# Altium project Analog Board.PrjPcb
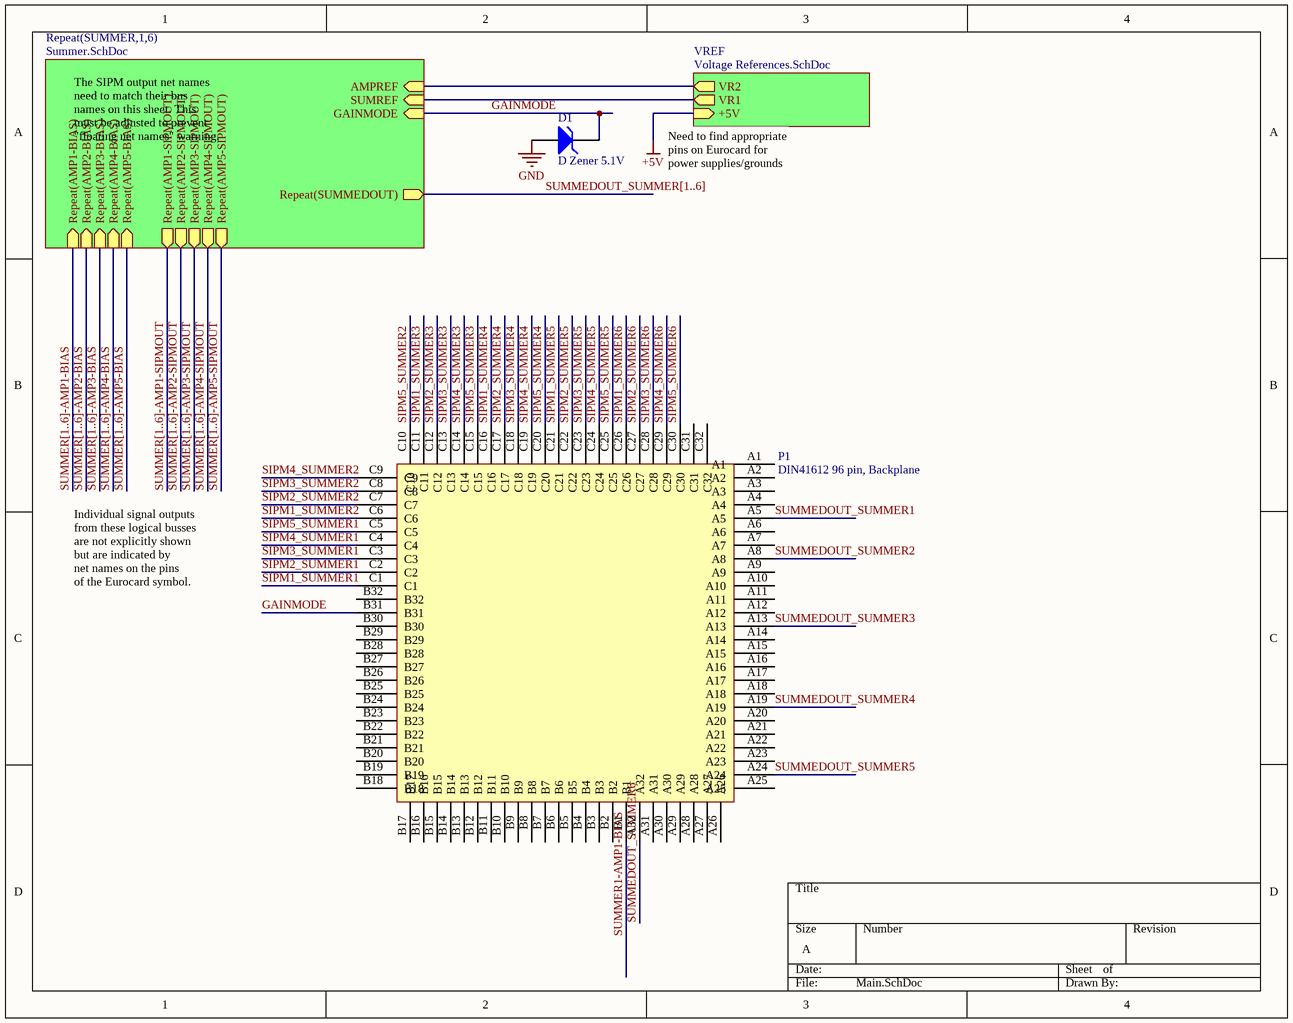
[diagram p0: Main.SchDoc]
4 sheets, 880 parts. Net scope: hierarchical (ports join the sheet entries above them; power ports are global).
Board files: Test PCB.PcbDoc, Amplifier Board.PcbDoc
Sheets:
  Main.SchDoc
    SUMMER1 = Summer.SchDoc
      AMP1 = Amplifier.SchDoc
      AMP2 = Amplifier.SchDoc
      AMP3 = Amplifier.SchDoc
      AMP4 = Amplifier.SchDoc
      AMP5 = Amplifier.SchDoc
    SUMMER2 = Summer.SchDoc
      AMP1 = Amplifier.SchDoc
      AMP2 = Amplifier.SchDoc
      AMP3 = Amplifier.SchDoc
      AMP4 = Amplifier.SchDoc
      AMP5 = Amplifier.SchDoc
    SUMMER3 = Summer.SchDoc
      AMP1 = Amplifier.SchDoc
      AMP2 = Amplifier.SchDoc
      AMP3 = Amplifier.SchDoc
      AMP4 = Amplifier.SchDoc
      AMP5 = Amplifier.SchDoc
    SUMMER4 = Summer.SchDoc
      AMP1 = Amplifier.SchDoc
      AMP2 = Amplifier.SchDoc
      AMP3 = Amplifier.SchDoc
      AMP4 = Amplifier.SchDoc
      AMP5 = Amplifier.SchDoc
    SUMMER5 = Summer.SchDoc
      AMP1 = Amplifier.SchDoc
      AMP2 = Amplifier.SchDoc
      AMP3 = Amplifier.SchDoc
      AMP4 = Amplifier.SchDoc
      AMP5 = Amplifier.SchDoc
    SUMMER6 = Summer.SchDoc
      AMP1 = Amplifier.SchDoc
      AMP2 = Amplifier.SchDoc
      AMP3 = Amplifier.SchDoc
      AMP4 = Amplifier.SchDoc
      AMP5 = Amplifier.SchDoc
    VREF = Voltage References.SchDoc

## Sheet Main.SchDoc
size A

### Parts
D1  D Zener 5.1V  [DIODE-0.7]
P1  DIN41612 96 pin, Backplane  [EURO2.54-2V96]

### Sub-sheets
Repeat(SUMMER,1,6) = Summer.SchDoc: Repeat(AMP1-BIAS) (in), Repeat(SUMMEDOUT) (out), Repeat(AMP2-SIPMOUT) (out), Repeat(AMP5-SIPMOUT) (out), Repeat(AMP1-SIPMOUT) (out), Repeat(AMP3-SIPMOUT) (out), Repeat(AMP4-SIPMOUT) (out), Repeat(AMP2-BIAS) (in), Repeat(AMP3-BIAS) (in), Repeat(AMP4-BIAS) (in), Repeat(AMP5-BIAS) (in), AMPREF (in), SUMREF (in), GAINMODE (in)
VREF = Voltage References.SchDoc: VR2 (out), VR1 (out), +5V (in)

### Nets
GND: D1.1(A)
GAINMODE: D1.2(K) P1.B31 ; sheet Repeat(SUMMER,1,6)/GAINMODE
SIPM1_SUMMER1: P1.C1
SIPM1_SUMMER2: P1.C6
SIPM1_SUMMER3: P1.C11
SIPM1_SUMMER4: P1.C16
SIPM1_SUMMER5: P1.C21
SIPM1_SUMMER6: P1.C26
SIPM2_SUMMER1: P1.C2
SIPM2_SUMMER2: P1.C7
SIPM2_SUMMER3: P1.C12
SIPM2_SUMMER4: P1.C17
SIPM2_SUMMER5: P1.C22
SIPM2_SUMMER6: P1.C27
SIPM3_SUMMER1: P1.C3
SIPM3_SUMMER2: P1.C8
SIPM3_SUMMER3: P1.C13
SIPM3_SUMMER4: P1.C18
SIPM3_SUMMER5: P1.C23
SIPM3_SUMMER6: P1.C28
SIPM4_SUMMER1: P1.C4
SIPM4_SUMMER2: P1.C9
SIPM4_SUMMER3: P1.C14
SIPM4_SUMMER4: P1.C19
SIPM4_SUMMER5: P1.C24
SIPM4_SUMMER6: P1.C29
SIPM5_SUMMER1: P1.C5
SIPM5_SUMMER2: P1.C10
SIPM5_SUMMER3: P1.C15
SIPM5_SUMMER4: P1.C20
SIPM5_SUMMER5: P1.C25
SIPM5_SUMMER6: P1.C30
SUMMEDOUT_SUMMER1: P1.A5
SUMMEDOUT_SUMMER2: P1.A8
SUMMEDOUT_SUMMER3: P1.A13
SUMMEDOUT_SUMMER4: P1.A19
SUMMEDOUT_SUMMER5: P1.A24
SUMMEDOUT_SUMMER6: P1.A32
SUMMER1-AMP1-BIAS: P1.B1
NetR25_2: sheet Repeat(SUMMER,1,6)/SUMREF, sheet VREF/VR1
NetR26_2: sheet Repeat(SUMMER,1,6)/AMPREF, sheet VREF/VR2

Not connected (* = marked no-connect by the designer): P1 A1 A2 A3 A4 A6 A7 A9 A10 A11 A12 A14 A15 A16 A17 A18 A20 A21 A22 A23 A25 A26 A27 A28 A29 A30 A31 B2 B3 B4 B5 B6 B7 B8 B9 B10 B11 B12 B13 B14 B15 B16 B17 B18 B19 B20 B21 B22 B23 B24 B25 B26 B27 B28 B29 B30 B32 C31 C32

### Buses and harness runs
bus SUMMEDOUT_SUMMER[1..6]
bus SUMMER[1..6]-AMP1-BIAS
bus SUMMER[1..6]-AMP1-SIPMOUT
bus SUMMER[1..6]-AMP2-BIAS
bus SUMMER[1..6]-AMP2-SIPMOUT
bus SUMMER[1..6]-AMP3-BIAS
bus SUMMER[1..6]-AMP3-SIPMOUT
bus SUMMER[1..6]-AMP4-BIAS
bus SUMMER[1..6]-AMP4-SIPMOUT
bus SUMMER[1..6]-AMP5-BIAS
bus SUMMER[1..6]-AMP5-SIPMOUT

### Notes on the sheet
- The SIPM output net names need to match their bus names on this sheet. This must be adjusted to prevent "floating net names" warning.
- Need to find appropriate pins on Eurocard for power supplies/grounds
- Individual signal outputs
  from these logical busses
  are not explicitly shown
  but are indicated by
  net names on the pins
  of the Eurocard symbol.

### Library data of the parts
D1 = D Zener: Zener Diode

## Sheet Summer.SchDoc
size A
Used 6 times, as channels SUMMER1, SUMMER2, SUMMER3, SUMMER4, SUMMER5, SUMMER6. Parts and nets are listed once, with the designators drawn on the sheet.
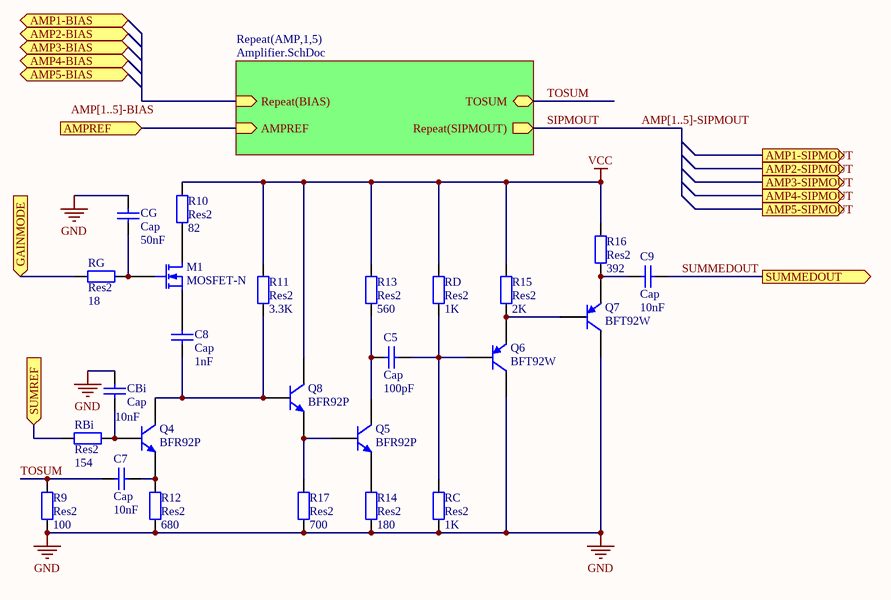
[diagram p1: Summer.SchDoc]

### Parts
C5  Cap  value 100pF  [RESC0603L]
C7  Cap  value 10nF  [RESC0603L]
C8  Cap  value 1nF  [RESC0603L]
C9  Cap  value 10nF  [RESC0603L]
CBi  Cap  value 10nF  [RESC0603L]
CG  Cap  value 50nF  [RESC0603L]
M1  MOSFET-N  [SOT-143]
Q4  BFR92P  [SOT23_N]
Q5  BFR92P  [SOT23_N]
Q6  BFT92W  [SOT323_L]
Q7  BFT92W  [SOT323_L]
Q8  BFR92P  [SOT23_N]
R9  Res2  value 100  [RESC0603L]
R10  Res2  value 82  [RESC0603L]
R11  Res2  value 3.3K  [RESC0603L]
R12  Res2  value 680  [RESC0603L]
R13  Res2  value 560  [RESC0603L]
R14  Res2  value 180  [RESC0603L]
R15  Res2  value 2K  [RESC0603L]
R16  Res2  value 392  [RESC0603L]
R17  Res2  value 700  [RESC0603L]
RBi  Res2  value 154  [RESC0603L]
RC  Res2  value 1K  [RESC0603L]
RD  Res2  value 1K  [RESC0603L]
RG  Res2  value 18  [RESC0603L]

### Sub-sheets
Repeat(AMP,1,5) = Amplifier.SchDoc: Repeat(BIAS) (in), TOSUM (bidir), Repeat(SIPMOUT) (out), AMPREF (in)

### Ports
AMP1-BIAS (in), AMP1-SIPMOUT (out), AMP2-BIAS (in), AMP2-SIPMOUT (out), AMP3-BIAS (in), AMP3-SIPMOUT (out), AMP4-BIAS (in), AMP4-SIPMOUT (out), AMP5-BIAS (in), AMP5-SIPMOUT (out), AMPREF (in), GAINMODE (in), SUMMEDOUT (out), SUMREF (in)

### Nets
GND: CBi.2 CG.2 Q6.3(C) Q7.3(C) R9.1 R12.1 R14.1 R17.1 RC.1
VCC: Q8.3(C) R10.2 R11.2 R13.2 R15.2 R16.2 RD.2
AMPREF: port AMPREF, sheet Repeat(AMP,1,5)/AMPREF
GAINMODE: RG.2 ; port GAINMODE
SUMMEDOUT: C9.2 ; port SUMMEDOUT
SUMREF: RBi.1 ; port SUMREF
TOSUM: C7.1 R9.2 ; sheet Repeat(AMP,1,5)/TOSUM
NetC5_1: C5.1 Q5.3(C) R13.1
NetC5_2: C5.2 Q6.1(B) RC.2 RD.1
NetC7_2: C7.2 Q4.2(E) R12.2
NetC8_1: C8.1 Q4.3(C) Q8.1(B) R11.1
NetC8_2: C8.2 M1.3(S)
NetC9_1: C9.1 Q7.2(E) R16.1
NetCBi_1: CBi.1 Q4.1(B) RBi.2
NetCG_1: CG.1 M1.1(G) RG.1
NetM1_4: M1.4(D) R10.1
NetQ5_1: Q5.1(B) Q8.2(E) R17.2
NetQ5_2: Q5.2(E) R14.2
NetQ6_2: Q6.2(E) Q7.1(B) R15.1

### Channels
SUMMER1: designators end in _SUMMER1; ports AMP1-BIAS=open AMP1-SIPMOUT=open AMP2-BIAS=open AMP2-SIPMOUT=open AMP3-BIAS=open AMP3-SIPMOUT=open AMP4-BIAS=open AMP4-SIPMOUT=open AMP5-BIAS=open AMP5-SIPMOUT=open AMPREF=NetR26_2 GAINMODE=GAINMODE SUMMEDOUT=SUMMEDOUT_SUMMER1 SUMREF=NetR25_2
SUMMER2: designators end in _SUMMER2; ports AMP1-BIAS=open AMP1-SIPMOUT=open AMP2-BIAS=open AMP2-SIPMOUT=open AMP3-BIAS=open AMP3-SIPMOUT=open AMP4-BIAS=open AMP4-SIPMOUT=open AMP5-BIAS=open AMP5-SIPMOUT=open AMPREF=NetR26_2 GAINMODE=GAINMODE SUMMEDOUT=SUMMEDOUT_SUMMER2 SUMREF=NetR25_2
SUMMER3: designators end in _SUMMER3; ports AMP1-BIAS=open AMP1-SIPMOUT=open AMP2-BIAS=open AMP2-SIPMOUT=open AMP3-BIAS=open AMP3-SIPMOUT=open AMP4-BIAS=open AMP4-SIPMOUT=open AMP5-BIAS=open AMP5-SIPMOUT=open AMPREF=NetR26_2 GAINMODE=GAINMODE SUMMEDOUT=SUMMEDOUT_SUMMER3 SUMREF=NetR25_2
SUMMER4: designators end in _SUMMER4; ports AMP1-BIAS=open AMP1-SIPMOUT=open AMP2-BIAS=open AMP2-SIPMOUT=open AMP3-BIAS=open AMP3-SIPMOUT=open AMP4-BIAS=open AMP4-SIPMOUT=open AMP5-BIAS=open AMP5-SIPMOUT=open AMPREF=NetR26_2 GAINMODE=GAINMODE SUMMEDOUT=SUMMEDOUT_SUMMER4 SUMREF=NetR25_2
SUMMER5: designators end in _SUMMER5; ports AMP1-BIAS=open AMP1-SIPMOUT=open AMP2-BIAS=open AMP2-SIPMOUT=open AMP3-BIAS=open AMP3-SIPMOUT=open AMP4-BIAS=open AMP4-SIPMOUT=open AMP5-BIAS=open AMP5-SIPMOUT=open AMPREF=NetR26_2 GAINMODE=GAINMODE SUMMEDOUT=SUMMEDOUT_SUMMER5 SUMREF=NetR25_2
SUMMER6: designators end in _SUMMER6; ports AMP1-BIAS=open AMP1-SIPMOUT=open AMP2-BIAS=open AMP2-SIPMOUT=open AMP3-BIAS=open AMP3-SIPMOUT=open AMP4-BIAS=open AMP4-SIPMOUT=open AMP5-BIAS=open AMP5-SIPMOUT=open AMPREF=NetR26_2 GAINMODE=GAINMODE SUMMEDOUT=SUMMEDOUT_SUMMER6 SUMREF=NetR25_2

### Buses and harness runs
bus AMP[1..5]-BIAS
bus AMP[1..5]-SIPMOUT

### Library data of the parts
C5 C7-C9 CBi CG = Cap: Capacitor
M1 = MOSFET-N: N-Channel MOSFET; PackageDocument: 1995/1996
Q4 Q5 Q8 = BFR92A: NPN 5 GHz Wideband Transistor
Q6 Q7 = BFT92W: PNP 4 GHz Wideband Transistor
R9-R17 RBi RC RD RG = Res2: Resistor

## Sheet Amplifier.SchDoc
size A
Used 30 times, as channels SUMMER1/AMP1, SUMMER1/AMP2, SUMMER1/AMP3, SUMMER1/AMP4, SUMMER1/AMP5, SUMMER2/AMP1, SUMMER2/AMP2, SUMMER2/AMP3, SUMMER2/AMP4, SUMMER2/AMP5, SUMMER3/AMP1, SUMMER3/AMP2, SUMMER3/AMP3, SUMMER3/AMP4, SUMMER3/AMP5, SUMMER4/AMP1, SUMMER4/AMP2, SUMMER4/AMP3, SUMMER4/AMP4, SUMMER4/AMP5, SUMMER5/AMP1, SUMMER5/AMP2, SUMMER5/AMP3, SUMMER5/AMP4, SUMMER5/AMP5, SUMMER6/AMP1, SUMMER6/AMP2, SUMMER6/AMP3, SUMMER6/AMP4, SUMMER6/AMP5. Parts and nets are listed once, with the designators drawn on the sheet.
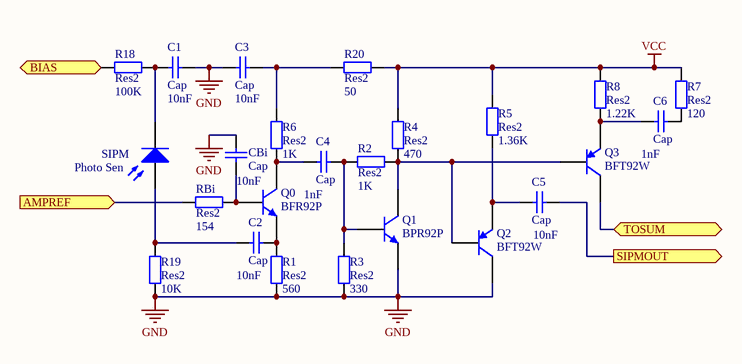
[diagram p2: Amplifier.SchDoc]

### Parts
C1  Cap  value 10nF  [RESC0603L]
C2  Cap  value 10nF  [RESC0603L]
C3  Cap  value 10nF  [RESC0603L]
C4  Cap  value 1nF  [RESC0603L]
C5  Cap  value 10nF  [RESC0603L]
C6  Cap  value 1nF  [RESC0603L]
CBi  Cap  value 10nF  [RESC0603L]
Q0  BFR92P  [SOT23_N]
Q1  BPR92P  [SOT23_N]
Q2  BFT92W  [SOT323_L]
Q3  BFT92W  [SOT323_L]
R1  Res2  value 560  [RESC0603L]
R2  Res2  value 1K  [RESC0603L]
R3  Res2  value 330  [RESC0603L]
R4  Res2  value 470  [RESC0603L]
R5  Res2  value 1.36K  [RESC0603L]
R6  Res2  value 1K  [RESC0603L]
R7  Res2  value 120  [RESC0603L]
R8  Res2  value 1.22K  [RESC0603L]
R18  Res2  value 100K  [RESC0603L]
R19  Res2  value 10K  [RESC0603L]
R20  Res2  value 50  [RESC0603L]
RBi  Res2  value 154  [RESC0603L]
SIPM  Photo Sen  [Photonique SiPM]

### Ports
AMPREF (in), BIAS (in), SIPMOUT (out), TOSUM (bidir)

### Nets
GND: C1.2 C3.1 CBi.2 Q1.2(E) Q2.3(C) R1.1 R3.1 R19.1
VCC: R4.2 R5.2 R7.2 R8.2 R20.2
AMPREF: RBi.1 ; port AMPREF
BIAS: R18.1 ; port BIAS
SIPMOUT: C5.2 ; port SIPMOUT
TOSUM: Q3.3(C) ; port TOSUM
NetC1_1: C1.1 R18.2 SIPM.2(K)
NetC2_1: C2.1 R19.2 SIPM.1(A)
NetC2_2: C2.2 Q0.2(E) R1.2
NetC3_2: C3.2 R6.2 R20.1
NetC4_1: C4.1 Q0.3(C) R6.1
NetC4_2: C4.2 Q1.1(B) R2.1 R3.2
NetC5_1: C5.1 Q2.2(E) R5.1
NetC6_1: C6.1 Q3.2(E) R8.1
NetC6_2: C6.2 R7.1
NetCBi_1: CBi.1 Q0.1(B) RBi.2
NetQ1_3: Q1.3(C) Q2.1(B) Q3.1(B) R2.2 R4.1

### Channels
SUMMER1/AMP1: designators end in _AMP1; ports AMPREF=NetR26_2 BIAS=NetR18_AMP1_1 SIPMOUT=SIPMOUT1_SUMMER1 TOSUM=TOSUM_SUMMER1
SUMMER1/AMP2: designators end in _AMP2; ports AMPREF=NetR26_2 BIAS=NetR18_AMP2_1 SIPMOUT=SIPMOUT2_SUMMER1 TOSUM=TOSUM_SUMMER1
SUMMER1/AMP3: designators end in _AMP3; ports AMPREF=NetR26_2 BIAS=NetR18_AMP3_1 SIPMOUT=SIPMOUT3_SUMMER1 TOSUM=TOSUM_SUMMER1
SUMMER1/AMP4: designators end in _AMP4; ports AMPREF=NetR26_2 BIAS=NetR18_AMP4_1 SIPMOUT=SIPMOUT4_SUMMER1 TOSUM=TOSUM_SUMMER1
SUMMER1/AMP5: designators end in _AMP5; ports AMPREF=NetR26_2 BIAS=NetR18_AMP5_1 SIPMOUT=SIPMOUT5_SUMMER1 TOSUM=TOSUM_SUMMER1
SUMMER2/AMP1: designators end in _AMP6; ports AMPREF=NetR26_2 BIAS=NetR18_AMP6_1 SIPMOUT=SIPMOUT1_SUMMER2 TOSUM=TOSUM_SUMMER2
SUMMER2/AMP2: designators end in _AMP7; ports AMPREF=NetR26_2 BIAS=NetR18_AMP7_1 SIPMOUT=SIPMOUT2_SUMMER2 TOSUM=TOSUM_SUMMER2
SUMMER2/AMP3: designators end in _AMP8; ports AMPREF=NetR26_2 BIAS=NetR18_AMP8_1 SIPMOUT=SIPMOUT3_SUMMER2 TOSUM=TOSUM_SUMMER2
SUMMER2/AMP4: designators end in _AMP9; ports AMPREF=NetR26_2 BIAS=NetR18_AMP9_1 SIPMOUT=SIPMOUT4_SUMMER2 TOSUM=TOSUM_SUMMER2
SUMMER2/AMP5: designators end in _AMP10; ports AMPREF=NetR26_2 BIAS=NetR18_AMP10_1 SIPMOUT=SIPMOUT5_SUMMER2 TOSUM=TOSUM_SUMMER2
SUMMER3/AMP1: designators end in _AMP11; ports AMPREF=NetR26_2 BIAS=NetR18_AMP11_1 SIPMOUT=SIPMOUT1_SUMMER3 TOSUM=TOSUM_SUMMER3
SUMMER3/AMP2: designators end in _AMP12; ports AMPREF=NetR26_2 BIAS=NetR18_AMP12_1 SIPMOUT=SIPMOUT2_SUMMER3 TOSUM=TOSUM_SUMMER3
SUMMER3/AMP3: designators end in _AMP13; ports AMPREF=NetR26_2 BIAS=NetR18_AMP13_1 SIPMOUT=SIPMOUT3_SUMMER3 TOSUM=TOSUM_SUMMER3
SUMMER3/AMP4: designators end in _AMP14; ports AMPREF=NetR26_2 BIAS=NetR18_AMP14_1 SIPMOUT=SIPMOUT4_SUMMER3 TOSUM=TOSUM_SUMMER3
SUMMER3/AMP5: designators end in _AMP15; ports AMPREF=NetR26_2 BIAS=NetR18_AMP15_1 SIPMOUT=SIPMOUT5_SUMMER3 TOSUM=TOSUM_SUMMER3
SUMMER4/AMP1: designators end in _AMP16; ports AMPREF=NetR26_2 BIAS=NetR18_AMP16_1 SIPMOUT=SIPMOUT1_SUMMER4 TOSUM=TOSUM_SUMMER4
SUMMER4/AMP2: designators end in _AMP17; ports AMPREF=NetR26_2 BIAS=NetR18_AMP17_1 SIPMOUT=SIPMOUT2_SUMMER4 TOSUM=TOSUM_SUMMER4
SUMMER4/AMP3: designators end in _AMP18; ports AMPREF=NetR26_2 BIAS=NetR18_AMP18_1 SIPMOUT=SIPMOUT3_SUMMER4 TOSUM=TOSUM_SUMMER4
SUMMER4/AMP4: designators end in _AMP19; ports AMPREF=NetR26_2 BIAS=NetR18_AMP19_1 SIPMOUT=SIPMOUT4_SUMMER4 TOSUM=TOSUM_SUMMER4
SUMMER4/AMP5: designators end in _AMP20; ports AMPREF=NetR26_2 BIAS=NetR18_AMP20_1 SIPMOUT=SIPMOUT5_SUMMER4 TOSUM=TOSUM_SUMMER4
SUMMER5/AMP1: designators end in _AMP21; ports AMPREF=NetR26_2 BIAS=NetR18_AMP21_1 SIPMOUT=SIPMOUT1_SUMMER5 TOSUM=TOSUM_SUMMER5
SUMMER5/AMP2: designators end in _AMP22; ports AMPREF=NetR26_2 BIAS=NetR18_AMP22_1 SIPMOUT=SIPMOUT2_SUMMER5 TOSUM=TOSUM_SUMMER5
SUMMER5/AMP3: designators end in _AMP23; ports AMPREF=NetR26_2 BIAS=NetR18_AMP23_1 SIPMOUT=SIPMOUT3_SUMMER5 TOSUM=TOSUM_SUMMER5
SUMMER5/AMP4: designators end in _AMP24; ports AMPREF=NetR26_2 BIAS=NetR18_AMP24_1 SIPMOUT=SIPMOUT4_SUMMER5 TOSUM=TOSUM_SUMMER5
SUMMER5/AMP5: designators end in _AMP25; ports AMPREF=NetR26_2 BIAS=NetR18_AMP25_1 SIPMOUT=SIPMOUT5_SUMMER5 TOSUM=TOSUM_SUMMER5
SUMMER6/AMP1: designators end in _AMP26; ports AMPREF=NetR26_2 BIAS=NetR18_AMP26_1 SIPMOUT=SIPMOUT1_SUMMER6 TOSUM=TOSUM_SUMMER6
SUMMER6/AMP2: designators end in _AMP27; ports AMPREF=NetR26_2 BIAS=NetR18_AMP27_1 SIPMOUT=SIPMOUT2_SUMMER6 TOSUM=TOSUM_SUMMER6
SUMMER6/AMP3: designators end in _AMP28; ports AMPREF=NetR26_2 BIAS=NetR18_AMP28_1 SIPMOUT=SIPMOUT3_SUMMER6 TOSUM=TOSUM_SUMMER6
SUMMER6/AMP4: designators end in _AMP29; ports AMPREF=NetR26_2 BIAS=NetR18_AMP29_1 SIPMOUT=SIPMOUT4_SUMMER6 TOSUM=TOSUM_SUMMER6
SUMMER6/AMP5: designators end in _AMP30; ports AMPREF=NetR26_2 BIAS=NetR18_AMP30_1 SIPMOUT=SIPMOUT5_SUMMER6 TOSUM=TOSUM_SUMMER6

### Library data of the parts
C1-C6 CBi = Cap: Capacitor
Q0 Q1 = BFR92A: NPN 5 GHz Wideband Transistor
Q2 Q3 = BFT92W: PNP 4 GHz Wideband Transistor
R1-R8 R18-R20 RBi = Res2: Resistor
SIPM = Photo Sen: Photosensitive Diode

## Sheet Voltage References.SchDoc
size A
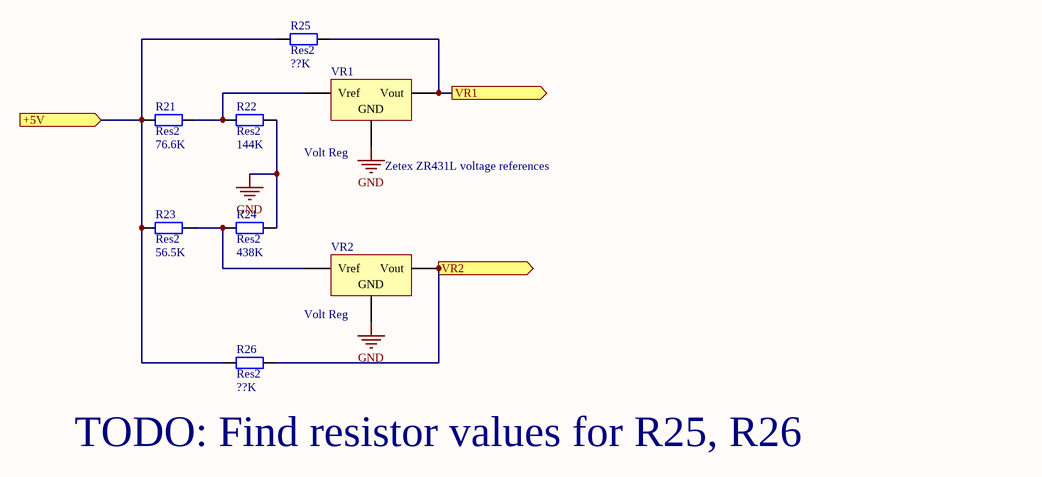
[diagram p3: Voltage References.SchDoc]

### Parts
R21  Res2  value 76.6K  [RESC0603L]
R22  Res2  value 144K  [RESC0603L]
R23  Res2  value 56.5K  [RESC3216L]
R24  Res2  value 438K  [RESC0603L]
R25  Res2  value ??K  [RESC0603L]
R26  Res2  value ??K  [RESC0603L]
VR1  Volt Reg  [SOT23_L]
VR2  Volt Reg  [SOT23_L]

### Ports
+5V (in), VR1 (out), VR2 (out)

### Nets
+5V: R21.1 R23.1 R25.1 R26.1 ; port +5V
GND: R22.2 R24.2 VR1.2(GND) VR2.2(GND)
NetR21_2: R21.2 R22.1 VR1.1(Vref)
NetR23_2: R23.2 R24.1 VR2.1(Vref)
NetR25_2: R25.2 VR1.3(Vout) ; port VR1
NetR26_2: R26.2 VR2.3(Vout) ; port VR2

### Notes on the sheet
- (near VR1) Zetex ZR431L voltage references
- (near R26) TODO: Find resistor values for R25, R26

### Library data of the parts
R21-R26 = Res2: Resistor
VR1 VR2 = Volt Reg: Voltage Regulator

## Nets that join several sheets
GND: Main (D1.1), SUMMER1 (9 pins), SUMMER1/AMP1 (8 pins), SUMMER1/AMP2 (8 pins), SUMMER1/AMP3 (8 pins), SUMMER1/AMP4 (8 pins), SUMMER1/AMP5 (8 pins), SUMMER2 (9 pins), SUMMER2/AMP1 (8 pins), SUMMER2/AMP2 (8 pins), SUMMER2/AMP3 (8 pins), SUMMER2/AMP4 (8 pins), SUMMER2/AMP5 (8 pins), SUMMER3 (9 pins), SUMMER3/AMP1 (8 pins), SUMMER3/AMP2 (8 pins), SUMMER3/AMP3 (8 pins), SUMMER3/AMP4 (8 pins), SUMMER3/AMP5 (8 pins), SUMMER4 (9 pins), SUMMER4/AMP1 (8 pins), SUMMER4/AMP2 (8 pins), SUMMER4/AMP3 (8 pins), SUMMER4/AMP4 (8 pins), SUMMER4/AMP5 (8 pins), SUMMER5 (9 pins), SUMMER5/AMP1 (8 pins), SUMMER5/AMP2 (8 pins), SUMMER5/AMP3 (8 pins), SUMMER5/AMP4 (8 pins), SUMMER5/AMP5 (8 pins), SUMMER6 (9 pins), SUMMER6/AMP1 (8 pins), SUMMER6/AMP2 (8 pins), SUMMER6/AMP3 (8 pins), SUMMER6/AMP4 (8 pins), SUMMER6/AMP5 (8 pins), Voltage References (R22.2 R24.2 VR1.2 VR2.2)
VCC: SUMMER1 (7 pins), SUMMER1/AMP1 (5 pins), SUMMER1/AMP2 (5 pins), SUMMER1/AMP3 (5 pins), SUMMER1/AMP4 (5 pins), SUMMER1/AMP5 (5 pins), SUMMER2 (7 pins), SUMMER2/AMP1 (5 pins), SUMMER2/AMP2 (5 pins), SUMMER2/AMP3 (5 pins), SUMMER2/AMP4 (5 pins), SUMMER2/AMP5 (5 pins), SUMMER3 (7 pins), SUMMER3/AMP1 (5 pins), SUMMER3/AMP2 (5 pins), SUMMER3/AMP3 (5 pins), SUMMER3/AMP4 (5 pins), SUMMER3/AMP5 (5 pins), SUMMER4 (7 pins), SUMMER4/AMP1 (5 pins), SUMMER4/AMP2 (5 pins), SUMMER4/AMP3 (5 pins), SUMMER4/AMP4 (5 pins), SUMMER4/AMP5 (5 pins), SUMMER5 (7 pins), SUMMER5/AMP1 (5 pins), SUMMER5/AMP2 (5 pins), SUMMER5/AMP3 (5 pins), SUMMER5/AMP4 (5 pins), SUMMER5/AMP5 (5 pins), SUMMER6 (7 pins), SUMMER6/AMP1 (5 pins), SUMMER6/AMP2 (5 pins), SUMMER6/AMP3 (5 pins), SUMMER6/AMP4 (5 pins), SUMMER6/AMP5 (5 pins)
GAINMODE: Main (D1.2 P1.B31), SUMMER1 (RG_SUMMER1.2), SUMMER2 (RG_SUMMER2.2), SUMMER3 (RG_SUMMER3.2), SUMMER4 (RG_SUMMER4.2), SUMMER5 (RG_SUMMER5.2), SUMMER6 (RG_SUMMER6.2)
NetR25_2: SUMMER1 (RBi_SUMMER1.1), SUMMER2 (RBi_SUMMER2.1), SUMMER3 (RBi_SUMMER3.1), SUMMER4 (RBi_SUMMER4.1), SUMMER5 (RBi_SUMMER5.1), SUMMER6 (RBi_SUMMER6.1), Voltage References (R25.2 VR1.3)
NetR26_2: SUMMER1/AMP1 (RBi_AMP1.1), SUMMER1/AMP2 (RBi_AMP2.1), SUMMER1/AMP3 (RBi_AMP3.1), SUMMER1/AMP4 (RBi_AMP4.1), SUMMER1/AMP5 (RBi_AMP5.1), SUMMER2/AMP1 (RBi_AMP6.1), SUMMER2/AMP2 (RBi_AMP7.1), SUMMER2/AMP3 (RBi_AMP8.1), SUMMER2/AMP4 (RBi_AMP9.1), SUMMER2/AMP5 (RBi_AMP10.1), SUMMER3/AMP1 (RBi_AMP11.1), SUMMER3/AMP2 (RBi_AMP12.1), SUMMER3/AMP3 (RBi_AMP13.1), SUMMER3/AMP4 (RBi_AMP14.1), SUMMER3/AMP5 (RBi_AMP15.1), SUMMER4/AMP1 (RBi_AMP16.1), SUMMER4/AMP2 (RBi_AMP17.1), SUMMER4/AMP3 (RBi_AMP18.1), SUMMER4/AMP4 (RBi_AMP19.1), SUMMER4/AMP5 (RBi_AMP20.1), SUMMER5/AMP1 (RBi_AMP21.1), SUMMER5/AMP2 (RBi_AMP22.1), SUMMER5/AMP3 (RBi_AMP23.1), SUMMER5/AMP4 (RBi_AMP24.1), SUMMER5/AMP5 (RBi_AMP25.1), SUMMER6/AMP1 (RBi_AMP26.1), SUMMER6/AMP2 (RBi_AMP27.1), SUMMER6/AMP3 (RBi_AMP28.1), SUMMER6/AMP4 (RBi_AMP29.1), SUMMER6/AMP5 (RBi_AMP30.1), Voltage References (R26.2 VR2.3)
TOSUM_SUMMER1: SUMMER1 (C7_SUMMER1.1 R9_SUMMER1.2), SUMMER1/AMP1 (Q3_AMP1.3), SUMMER1/AMP2 (Q3_AMP2.3), SUMMER1/AMP3 (Q3_AMP3.3), SUMMER1/AMP4 (Q3_AMP4.3), SUMMER1/AMP5 (Q3_AMP5.3)
TOSUM_SUMMER2: SUMMER2 (C7_SUMMER2.1 R9_SUMMER2.2), SUMMER2/AMP1 (Q3_AMP6.3), SUMMER2/AMP2 (Q3_AMP7.3), SUMMER2/AMP3 (Q3_AMP8.3), SUMMER2/AMP4 (Q3_AMP9.3), SUMMER2/AMP5 (Q3_AMP10.3)
TOSUM_SUMMER3: SUMMER3 (C7_SUMMER3.1 R9_SUMMER3.2), SUMMER3/AMP1 (Q3_AMP11.3), SUMMER3/AMP2 (Q3_AMP12.3), SUMMER3/AMP3 (Q3_AMP13.3), SUMMER3/AMP4 (Q3_AMP14.3), SUMMER3/AMP5 (Q3_AMP15.3)
TOSUM_SUMMER4: SUMMER4 (C7_SUMMER4.1 R9_SUMMER4.2), SUMMER4/AMP1 (Q3_AMP16.3), SUMMER4/AMP2 (Q3_AMP17.3), SUMMER4/AMP3 (Q3_AMP18.3), SUMMER4/AMP4 (Q3_AMP19.3), SUMMER4/AMP5 (Q3_AMP20.3)
TOSUM_SUMMER5: SUMMER5 (C7_SUMMER5.1 R9_SUMMER5.2), SUMMER5/AMP1 (Q3_AMP21.3), SUMMER5/AMP2 (Q3_AMP22.3), SUMMER5/AMP3 (Q3_AMP23.3), SUMMER5/AMP4 (Q3_AMP24.3), SUMMER5/AMP5 (Q3_AMP25.3)
TOSUM_SUMMER6: SUMMER6 (C7_SUMMER6.1 R9_SUMMER6.2), SUMMER6/AMP1 (Q3_AMP26.3), SUMMER6/AMP2 (Q3_AMP27.3), SUMMER6/AMP3 (Q3_AMP28.3), SUMMER6/AMP4 (Q3_AMP29.3), SUMMER6/AMP5 (Q3_AMP30.3)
